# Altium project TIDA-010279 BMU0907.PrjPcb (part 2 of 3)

## Sheet TIDA-010279 BMU_stack0.SchDoc
size 558 x 431 mm; Date: Not shown in title block; ApprovedBy: Not shown in title block; CheckedBy: Not shown in title block; Author: Not shown in title block; CompanyName: Not shown in title block; Engineer: Not shown in title block; Organization: Not shown in title block; Address1: Not shown in title block; Address2: Not shown in title block; Address3: Not shown in title block; Address4: Not shown in title block; DocumentNumber: 2; Revision: Use project parameter SCH_Rev; SheetNumber: 2; SheetTotal: 4; PageSetup: Record=PageOptions¦CenterHorizontal=True¦CenterVertical=True¦PrintScale=1.00¦XCorrection=1.00¦YCorrection=1.00¦PrintKind=0¦BorderSize=5000000¦LeftOffset=0¦BottomOffset=0¦Orientation=2¦PaperLength=1000¦PaperWidth=1000¦Scale=100¦PaperSource=15¦PrintQuality=600¦MediaType=1¦DitherType=10¦PaperKind=Letter¦PrintScaleMode=1
Used 4 times, as channels A1, A2, A3, A4. Parts and nets are listed once, with the designators drawn on the sheet.
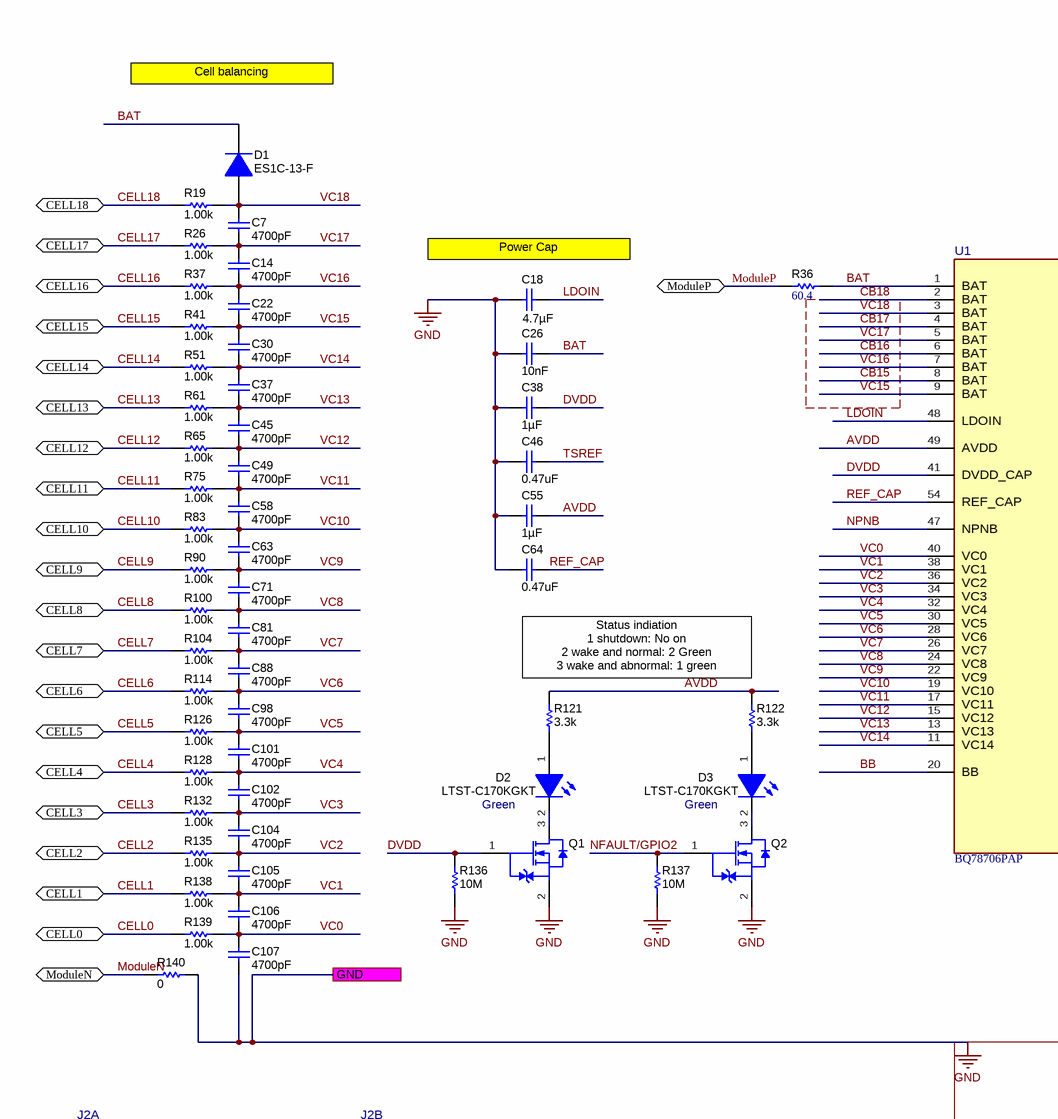
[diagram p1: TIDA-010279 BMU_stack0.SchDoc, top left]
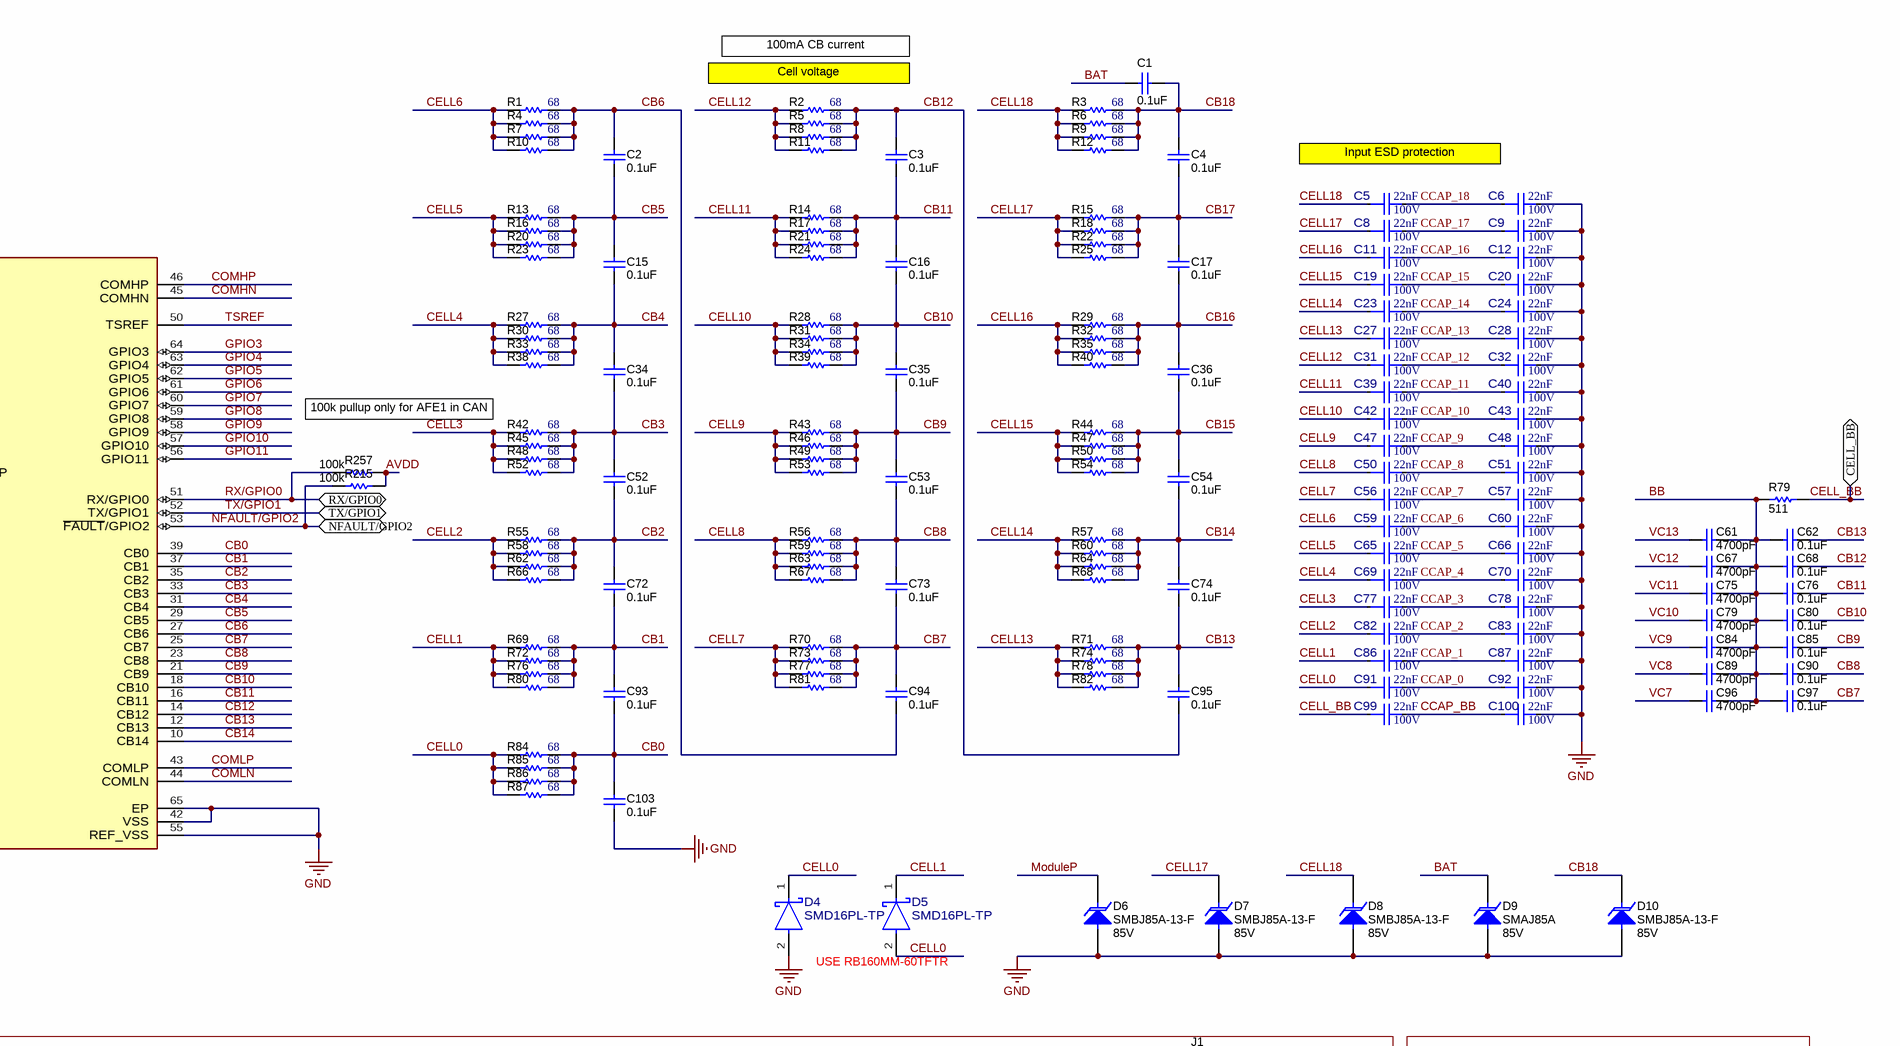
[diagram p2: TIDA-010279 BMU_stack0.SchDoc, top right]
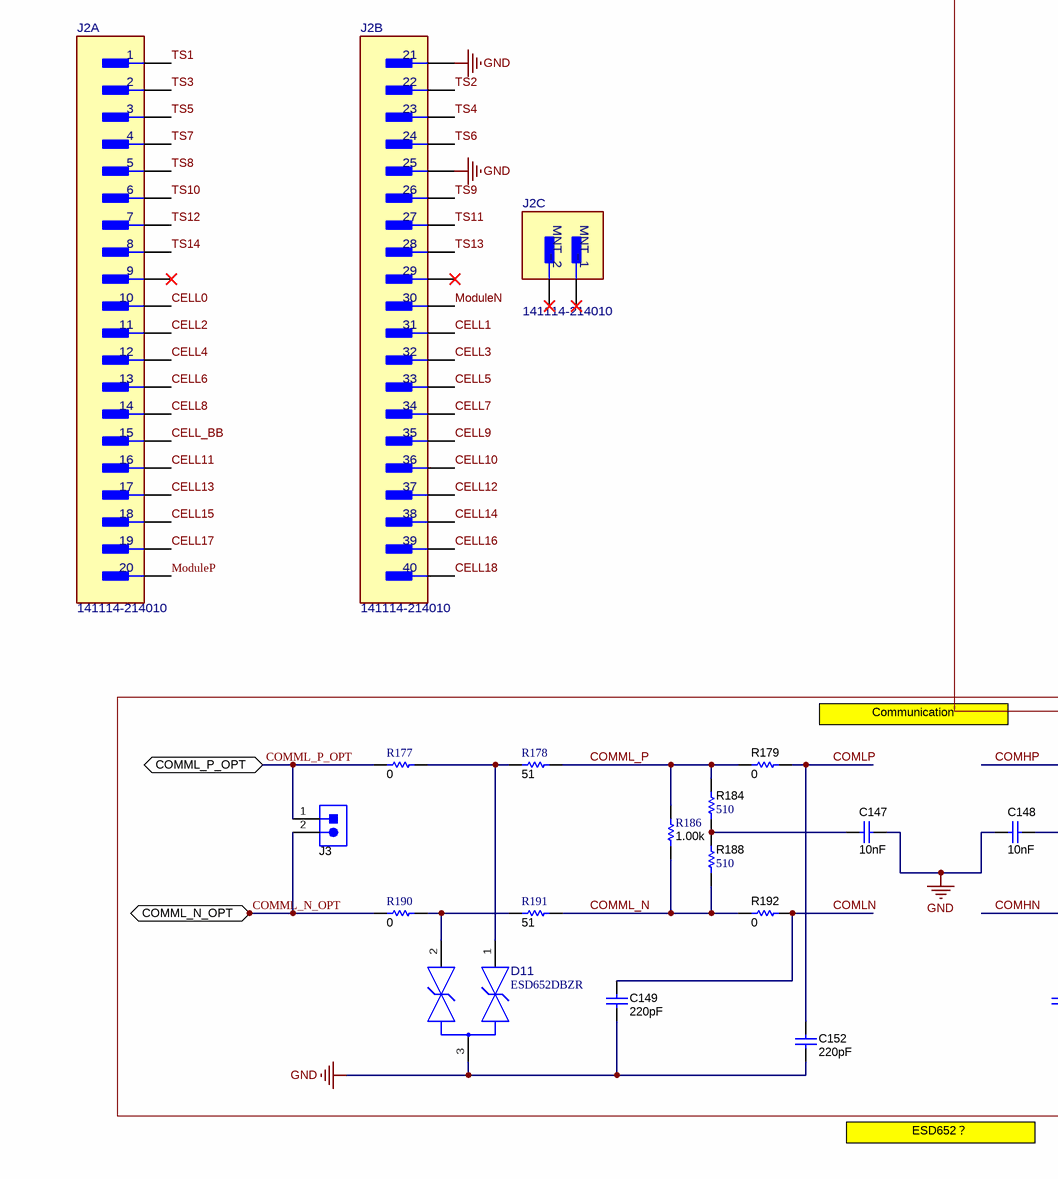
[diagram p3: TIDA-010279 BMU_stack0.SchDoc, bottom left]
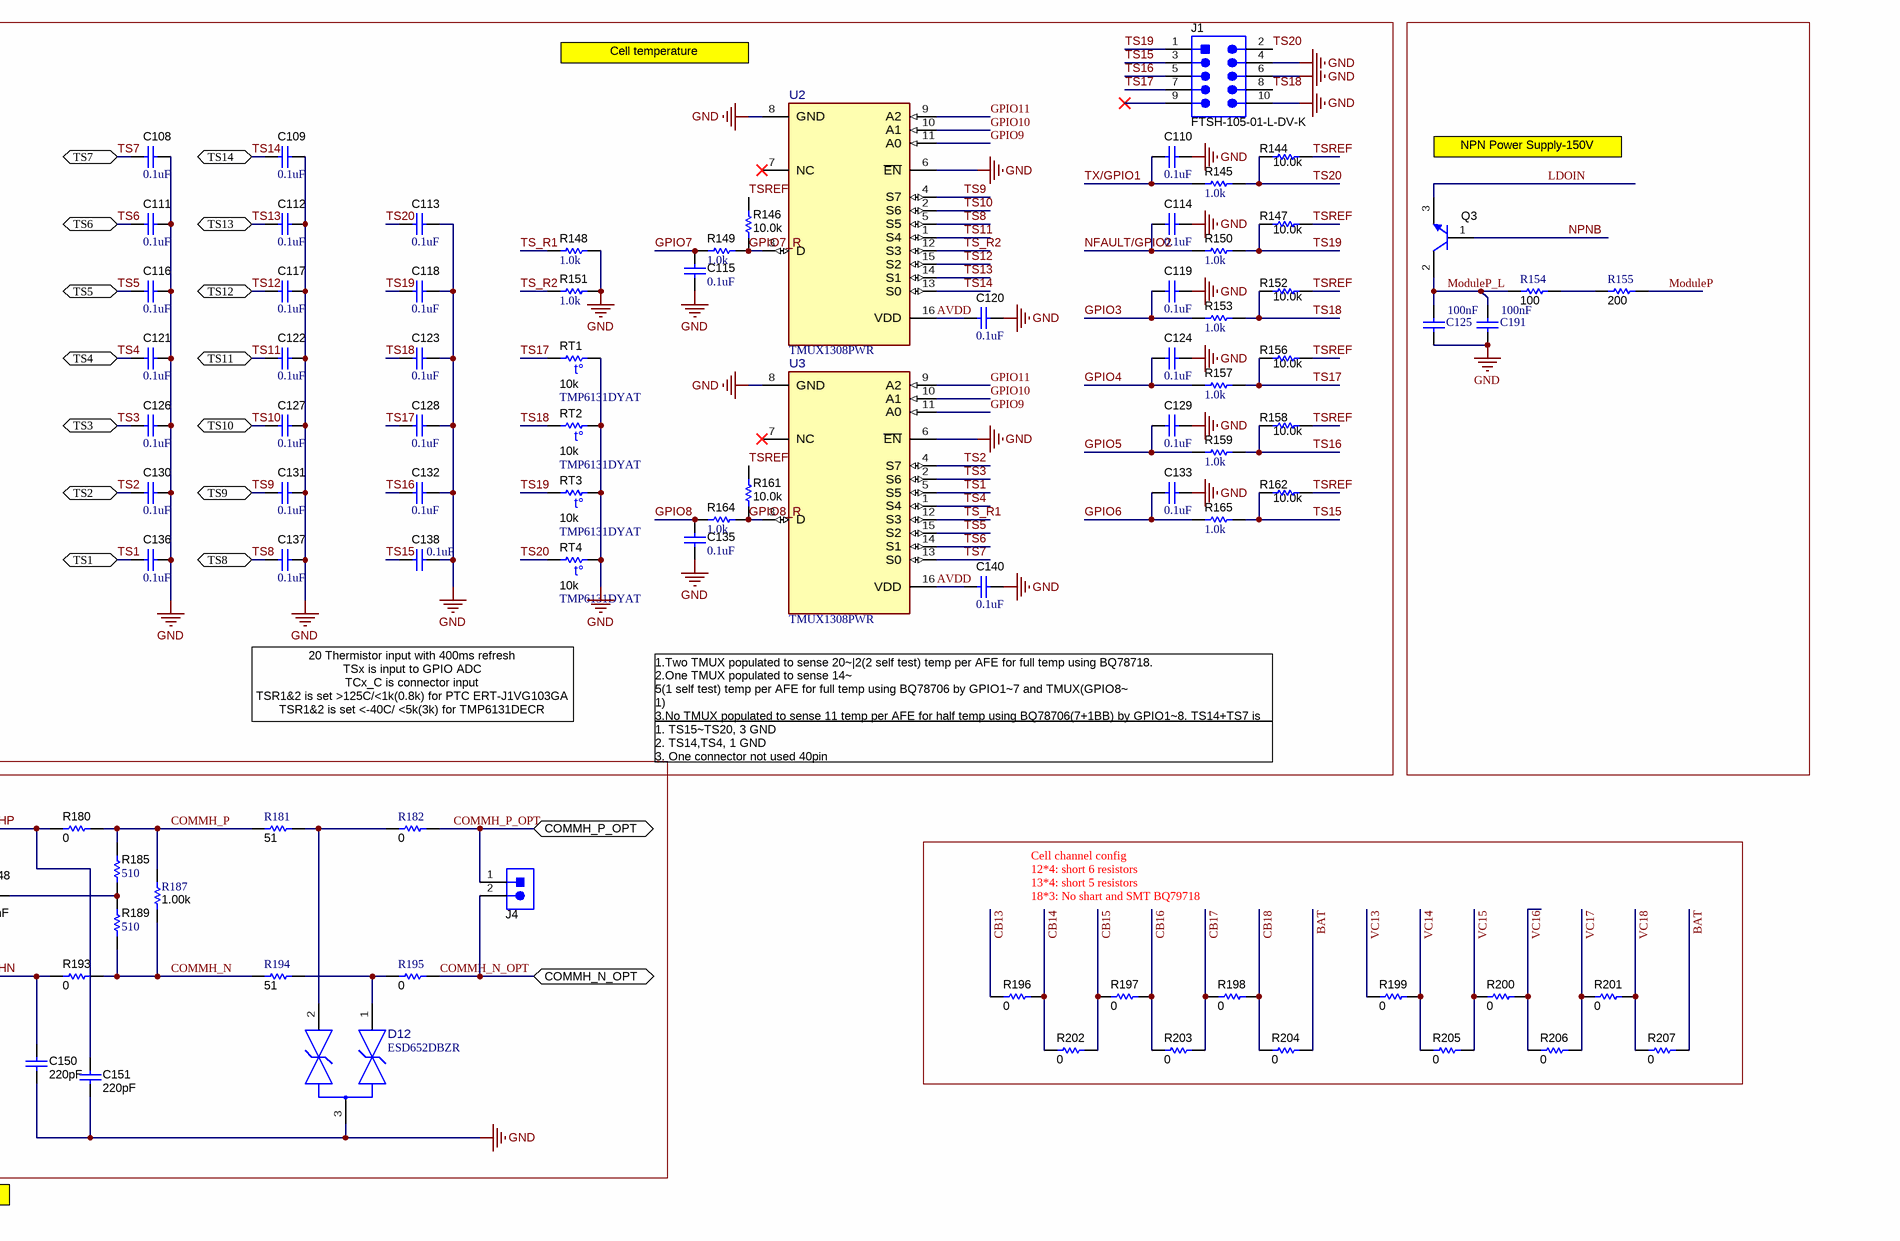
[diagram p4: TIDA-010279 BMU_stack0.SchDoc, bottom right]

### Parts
C1  ValueDisplayed: 0.1uF  [0402]  (hidden comment: GCM155R71H104KE02D)
C2  ValueDisplayed: 0.1uF  [0402]  (hidden comment: GCM155R71H104KE02D)
C3  ValueDisplayed: 0.1uF  [0402]  (hidden comment: GCM155R71H104KE02D)
C4  ValueDisplayed: 0.1uF  [0402]  (hidden comment: GCM155R71H104KE02D)
C5  VDC_V: 100V  Cap_F: 22nF  [FP-CGA3E2X7R2A223K080AA_0603-MFG]  (hidden comment: CGA3E2X7R2A223K080AA)
C6  VDC_V: 100V  Cap_F: 22nF  [FP-CGA3E2X7R2A223K080AA_0603-MFG]  (hidden comment: CGA3E2X7R2A223K080AA)
C7  ValueDisplayed: 4700pF  [0402]  (hidden comment: GCM155R71H472KA37D)
C8  VDC_V: 100V  Cap_F: 22nF  [FP-CGA3E2X7R2A223K080AA_0603-MFG]  (hidden comment: CGA3E2X7R2A223K080AA)
C9  VDC_V: 100V  Cap_F: 22nF  [FP-CGA3E2X7R2A223K080AA_0603-MFG]  (hidden comment: CGA3E2X7R2A223K080AA)
C11  VDC_V: 100V  Cap_F: 22nF  [FP-CGA3E2X7R2A223K080AA_0603-MFG]  (hidden comment: CGA3E2X7R2A223K080AA)
C12  VDC_V: 100V  Cap_F: 22nF  [FP-CGA3E2X7R2A223K080AA_0603-MFG]  (hidden comment: CGA3E2X7R2A223K080AA)
C14  ValueDisplayed: 4700pF  [0402]  (hidden comment: GCM155R71H472KA37D)
C15  ValueDisplayed: 0.1uF  [0402]  (hidden comment: GCM155R71H104KE02D)
C16  ValueDisplayed: 0.1uF  [0402]  (hidden comment: GCM155R71H104KE02D)
C17  ValueDisplayed: 0.1uF  [0402]  (hidden comment: GCM155R71H104KE02D)
C18  Cap_F: 4.7µF  [0805_HV]  (hidden comment: C0805C475J8RACAUTO)
C19  VDC_V: 100V  Cap_F: 22nF  [FP-CGA3E2X7R2A223K080AA_0603-MFG]  (hidden comment: CGA3E2X7R2A223K080AA)
C20  VDC_V: 100V  Cap_F: 22nF  [FP-CGA3E2X7R2A223K080AA_0603-MFG]  (hidden comment: CGA3E2X7R2A223K080AA)
C22  ValueDisplayed: 4700pF  [0402]  (hidden comment: GCM155R71H472KA37D)
C23  VDC_V: 100V  Cap_F: 22nF  [FP-CGA3E2X7R2A223K080AA_0603-MFG]  (hidden comment: CGA3E2X7R2A223K080AA)
C24  VDC_V: 100V  Cap_F: 22nF  [FP-CGA3E2X7R2A223K080AA_0603-MFG]  (hidden comment: CGA3E2X7R2A223K080AA)
C26  Cap_F: 10nF  [0603_HV]  (hidden comment: GCM188R72A103KA37J)
C27  VDC_V: 100V  Cap_F: 22nF  [FP-CGA3E2X7R2A223K080AA_0603-MFG]  (hidden comment: CGA3E2X7R2A223K080AA)
C28  VDC_V: 100V  Cap_F: 22nF  [FP-CGA3E2X7R2A223K080AA_0603-MFG]  (hidden comment: CGA3E2X7R2A223K080AA)
C30  ValueDisplayed: 4700pF  [0402]  (hidden comment: GCM155R71H472KA37D)
C31  VDC_V: 100V  Cap_F: 22nF  [FP-CGA3E2X7R2A223K080AA_0603-MFG]  (hidden comment: CGA3E2X7R2A223K080AA)
C32  VDC_V: 100V  Cap_F: 22nF  [FP-CGA3E2X7R2A223K080AA_0603-MFG]  (hidden comment: CGA3E2X7R2A223K080AA)
C34  ValueDisplayed: 0.1uF  [0402]  (hidden comment: GCM155R71H104KE02D)
C35  ValueDisplayed: 0.1uF  [0402]  (hidden comment: GCM155R71H104KE02D)
C36  ValueDisplayed: 0.1uF  [0402]  (hidden comment: GCM155R71H104KE02D)
C37  ValueDisplayed: 4700pF  [0402]  (hidden comment: GCM155R71H472KA37D)
C38  Cap_F: 1µF  [0603]  (hidden comment: GCM188R71C105KA64D)
C39  VDC_V: 100V  Cap_F: 22nF  [FP-CGA3E2X7R2A223K080AA_0603-MFG]  (hidden comment: CGA3E2X7R2A223K080AA)
C40  VDC_V: 100V  Cap_F: 22nF  [FP-CGA3E2X7R2A223K080AA_0603-MFG]  (hidden comment: CGA3E2X7R2A223K080AA)
C42  VDC_V: 100V  Cap_F: 22nF  [FP-CGA3E2X7R2A223K080AA_0603-MFG]  (hidden comment: CGA3E2X7R2A223K080AA)
C43  VDC_V: 100V  Cap_F: 22nF  [FP-CGA3E2X7R2A223K080AA_0603-MFG]  (hidden comment: CGA3E2X7R2A223K080AA)
C45  ValueDisplayed: 4700pF  [0402]  (hidden comment: GCM155R71H472KA37D)
C46  ValueDisplayed: 0.47uF  [0603]  (hidden comment: GCM188R71C474KA55D)
C47  VDC_V: 100V  Cap_F: 22nF  [FP-CGA3E2X7R2A223K080AA_0603-MFG]  (hidden comment: CGA3E2X7R2A223K080AA)
C48  VDC_V: 100V  Cap_F: 22nF  [FP-CGA3E2X7R2A223K080AA_0603-MFG]  (hidden comment: CGA3E2X7R2A223K080AA)
C49  ValueDisplayed: 4700pF  [0402]  (hidden comment: GCM155R71H472KA37D)
C50  VDC_V: 100V  Cap_F: 22nF  [FP-CGA3E2X7R2A223K080AA_0603-MFG]  (hidden comment: CGA3E2X7R2A223K080AA)
C51  VDC_V: 100V  Cap_F: 22nF  [FP-CGA3E2X7R2A223K080AA_0603-MFG]  (hidden comment: CGA3E2X7R2A223K080AA)
C52  ValueDisplayed: 0.1uF  [0402]  (hidden comment: GCM155R71H104KE02D)
C53  ValueDisplayed: 0.1uF  [0402]  (hidden comment: GCM155R71H104KE02D)
C54  ValueDisplayed: 0.1uF  [0402]  (hidden comment: GCM155R71H104KE02D)
C55  Cap_F: 1µF  [0603]  (hidden comment: GCM188R71C105KA64D)
C56  VDC_V: 100V  Cap_F: 22nF  [FP-CGA3E2X7R2A223K080AA_0603-MFG]  (hidden comment: CGA3E2X7R2A223K080AA)
C57  VDC_V: 100V  Cap_F: 22nF  [FP-CGA3E2X7R2A223K080AA_0603-MFG]  (hidden comment: CGA3E2X7R2A223K080AA)
C58  ValueDisplayed: 4700pF  [0402]  (hidden comment: GCM155R71H472KA37D)
C59  VDC_V: 100V  Cap_F: 22nF  [FP-CGA3E2X7R2A223K080AA_0603-MFG]  (hidden comment: CGA3E2X7R2A223K080AA)
C60  VDC_V: 100V  Cap_F: 22nF  [FP-CGA3E2X7R2A223K080AA_0603-MFG]  (hidden comment: CGA3E2X7R2A223K080AA)
C61  ValueDisplayed: 4700pF  [0402]  (hidden comment: GCM155R71H472KA37D)
C62  ValueDisplayed: 0.1uF  [0402]  (hidden comment: GCM155R71H104KE02D)
C63  ValueDisplayed: 4700pF  [0402]  (hidden comment: GCM155R71H472KA37D)
C64  ValueDisplayed: 0.47uF  [0603]  (hidden comment: GCM188R71C474KA55D)
C65  VDC_V: 100V  Cap_F: 22nF  [FP-CGA3E2X7R2A223K080AA_0603-MFG]  (hidden comment: CGA3E2X7R2A223K080AA)
C66  VDC_V: 100V  Cap_F: 22nF  [FP-CGA3E2X7R2A223K080AA_0603-MFG]  (hidden comment: CGA3E2X7R2A223K080AA)
C67  ValueDisplayed: 4700pF  [0402]  (hidden comment: GCM155R71H472KA37D)
C68  ValueDisplayed: 0.1uF  [0402]  (hidden comment: GCM155R71H104KE02D)
C69  VDC_V: 100V  Cap_F: 22nF  [FP-CGA3E2X7R2A223K080AA_0603-MFG]  (hidden comment: CGA3E2X7R2A223K080AA)
C70  VDC_V: 100V  Cap_F: 22nF  [FP-CGA3E2X7R2A223K080AA_0603-MFG]  (hidden comment: CGA3E2X7R2A223K080AA)
C71  ValueDisplayed: 4700pF  [0402]  (hidden comment: GCM155R71H472KA37D)
C72  ValueDisplayed: 0.1uF  [0402]  (hidden comment: GCM155R71H104KE02D)
C73  ValueDisplayed: 0.1uF  [0402]  (hidden comment: GCM155R71H104KE02D)
C74  ValueDisplayed: 0.1uF  [0402]  (hidden comment: GCM155R71H104KE02D)
C75  ValueDisplayed: 4700pF  [0402]  (hidden comment: GCM155R71H472KA37D)
C76  ValueDisplayed: 0.1uF  [0402]  (hidden comment: GCM155R71H104KE02D)
C77  VDC_V: 100V  Cap_F: 22nF  [FP-CGA3E2X7R2A223K080AA_0603-MFG]  (hidden comment: CGA3E2X7R2A223K080AA)
C78  VDC_V: 100V  Cap_F: 22nF  [FP-CGA3E2X7R2A223K080AA_0603-MFG]  (hidden comment: CGA3E2X7R2A223K080AA)
C79  ValueDisplayed: 4700pF  [0402]  (hidden comment: GCM155R71H472KA37D)
C80  ValueDisplayed: 0.1uF  [0402]  (hidden comment: GCM155R71H104KE02D)
C81  ValueDisplayed: 4700pF  [0402]  (hidden comment: GCM155R71H472KA37D)
C82  VDC_V: 100V  Cap_F: 22nF  [FP-CGA3E2X7R2A223K080AA_0603-MFG]  (hidden comment: CGA3E2X7R2A223K080AA)
C83  VDC_V: 100V  Cap_F: 22nF  [FP-CGA3E2X7R2A223K080AA_0603-MFG]  (hidden comment: CGA3E2X7R2A223K080AA)
C84  ValueDisplayed: 4700pF  [0402]  (hidden comment: GCM155R71H472KA37D)
C85  ValueDisplayed: 0.1uF  [0402]  (hidden comment: GCM155R71H104KE02D)
C86  VDC_V: 100V  Cap_F: 22nF  [FP-CGA3E2X7R2A223K080AA_0603-MFG]  (hidden comment: CGA3E2X7R2A223K080AA)
C87  VDC_V: 100V  Cap_F: 22nF  [FP-CGA3E2X7R2A223K080AA_0603-MFG]  (hidden comment: CGA3E2X7R2A223K080AA)
C88  ValueDisplayed: 4700pF  [0402]  (hidden comment: GCM155R71H472KA37D)
C89  ValueDisplayed: 4700pF  [0402]  (hidden comment: GCM155R71H472KA37D)
C90  ValueDisplayed: 0.1uF  [0402]  (hidden comment: GCM155R71H104KE02D)
C91  VDC_V: 100V  Cap_F: 22nF  [FP-CGA3E2X7R2A223K080AA_0603-MFG]  (hidden comment: CGA3E2X7R2A223K080AA)
C92  VDC_V: 100V  Cap_F: 22nF  [FP-CGA3E2X7R2A223K080AA_0603-MFG]  (hidden comment: CGA3E2X7R2A223K080AA)
C93  ValueDisplayed: 0.1uF  [0402]  (hidden comment: GCM155R71H104KE02D)
C94  ValueDisplayed: 0.1uF  [0402]  (hidden comment: GCM155R71H104KE02D)
C95  ValueDisplayed: 0.1uF  [0402]  (hidden comment: GCM155R71H104KE02D)
C96  ValueDisplayed: 4700pF  [0402]  (hidden comment: GCM155R71H472KA37D)
C97  ValueDisplayed: 0.1uF  [0402]  (hidden comment: GCM155R71H104KE02D)
C98  ValueDisplayed: 4700pF  [0402]  (hidden comment: GCM155R71H472KA37D)
C99  VDC_V: 100V  Cap_F: 22nF  [FP-CGA3E2X7R2A223K080AA_0603-MFG]  (hidden comment: CGA3E2X7R2A223K080AA)
C100  VDC_V: 100V  Cap_F: 22nF  [FP-CGA3E2X7R2A223K080AA_0603-MFG]  (hidden comment: CGA3E2X7R2A223K080AA)
C101  ValueDisplayed: 4700pF  [0402]  (hidden comment: GCM155R71H472KA37D)
C102  ValueDisplayed: 4700pF  [0402]  (hidden comment: GCM155R71H472KA37D)
C103  ValueDisplayed: 0.1uF  [0402]  (hidden comment: GCM155R71H104KE02D)
C104  ValueDisplayed: 4700pF  [0402]  (hidden comment: GCM155R71H472KA37D)
C105  ValueDisplayed: 4700pF  [0402]  (hidden comment: GCM155R71H472KA37D)
C106  ValueDisplayed: 4700pF  [0402]  (hidden comment: GCM155R71H472KA37D)
C107  ValueDisplayed: 4700pF  [0402]  (hidden comment: GCM155R71H472KA37D)
C108  ValueDisplayed: 0.1uF  [0402]  (hidden comment: GCM155R71H104KE02D)
C109  ValueDisplayed: 0.1uF  [0402]  (hidden comment: GCM155R71H104KE02D)
C110  ValueDisplayed: 0.1uF  [0402]  (hidden comment: GCM155R71H104KE02D)
C111  ValueDisplayed: 0.1uF  [0402]  (hidden comment: GCM155R71H104KE02D)
C112  ValueDisplayed: 0.1uF  [0402]  (hidden comment: GCM155R71H104KE02D)
C113  ValueDisplayed: 0.1uF  [0402]  (hidden comment: GCM155R71H104KE02D)
C114  ValueDisplayed: 0.1uF  [0402]  (hidden comment: GCM155R71H104KE02D)
C115  ValueDisplayed: 0.1uF  [0402]  (hidden comment: GCM155R71H104KE02D)
C116  ValueDisplayed: 0.1uF  [0402]  (hidden comment: GCM155R71H104KE02D)
C117  ValueDisplayed: 0.1uF  [0402]  (hidden comment: GCM155R71H104KE02D)
C118  ValueDisplayed: 0.1uF  [0402]  (hidden comment: GCM155R71H104KE02D)
C119  ValueDisplayed: 0.1uF  [0402]  (hidden comment: GCM155R71H104KE02D)
C120  ValueDisplayed: 0.1uF  [0402]  (hidden comment: GCM155R71H104KE02D)
C121  ValueDisplayed: 0.1uF  [0402]  (hidden comment: GCM155R71H104KE02D)
C122  ValueDisplayed: 0.1uF  [0402]  (hidden comment: GCM155R71H104KE02D)
C123  ValueDisplayed: 0.1uF  [0402]  (hidden comment: GCM155R71H104KE02D)
C124  ValueDisplayed: 0.1uF  [0402]  (hidden comment: GCM155R71H104KE02D)
C125  Cap_F: 100nF  [WCAP-CSGP_1206_L3.2W1.6H1.25]  (hidden comment: 885012208118)
C126  ValueDisplayed: 0.1uF  [0402]  (hidden comment: GCM155R71H104KE02D)
C127  ValueDisplayed: 0.1uF  [0402]  (hidden comment: GCM155R71H104KE02D)
C128  ValueDisplayed: 0.1uF  [0402]  (hidden comment: GCM155R71H104KE02D)
C129  ValueDisplayed: 0.1uF  [0402]  (hidden comment: GCM155R71H104KE02D)
C130  ValueDisplayed: 0.1uF  [0402]  (hidden comment: GCM155R71H104KE02D)
C131  ValueDisplayed: 0.1uF  [0402]  (hidden comment: GCM155R71H104KE02D)
C132  ValueDisplayed: 0.1uF  [0402]  (hidden comment: GCM155R71H104KE02D)
C133  ValueDisplayed: 0.1uF  [0402]  (hidden comment: GCM155R71H104KE02D)
C135  ValueDisplayed: 0.1uF  [0402]  (hidden comment: GCM155R71H104KE02D)
C136  ValueDisplayed: 0.1uF  [0402]  (hidden comment: GCM155R71H104KE02D)
C137  ValueDisplayed: 0.1uF  [0402]  (hidden comment: GCM155R71H104KE02D)
C138  ValueDisplayed: 0.1uF  [0402]  (hidden comment: GCM155R71H104KE02D)
C140  ValueDisplayed: 0.1uF  [0402]  (hidden comment: GCM155R71H104KE02D)
C147  Cap_F: 10nF  [0603]  (hidden comment: GCM188R71H103KA37D)
C148  Cap_F: 10nF  [0603]  (hidden comment: GCM188R71H103KA37D)
C149  Cap_F: 220pF  [0603]  (hidden comment: CL10B221JB8NNNC)
C150  Cap_F: 220pF  [0603]  (hidden comment: CL10B221JB8NNNC)
C151  Cap_F: 220pF  [0603]  (hidden comment: CL10B221JB8NNNC)
C152  Cap_F: 220pF  [0603]  (hidden comment: CL10B221JB8NNNC)
C191  Cap_F: 100nF  [WCAP-CSGP_1206_L3.2W1.6H1.25]  (hidden comment: 885012208118)
D1  ES1C-13-F  [SMA]
D2  LTST-C170KGKT  value Green  [LTST-C170KGKT_Green]
D3  LTST-C170KGKT  value Green  [LTST-C170KGKT_Green]
D4  SMD16PL-TP  [FP-SMD16PL-TP_SOD123FL-MFG]
D5  SMD16PL-TP  [FP-SMD16PL-TP_SOD123FL-MFG]
D6  SMBJ85A-13-F  value 85V  [SMB]
D7  SMBJ85A-13-F  value 85V  [SMB]
D8  SMBJ85A-13-F  value 85V  [SMB]
D9  SMAJ85A  value 85V  [SMA]
D10  SMBJ85A-13-F  value 85V  [SMB]
D11  ESD652DBZR  [DBZ0003A-MFG]
D12  ESD652DBZR  [DBZ0003A-MFG]
J1  FTSH-105-01-L-DV-K  [Samtec_FTSH-105-01-x-DV-K]
J2  141114-214010  [FP-141114-214010_HDR40-MFG]  (parts A,B,C of 3)
J3  PEC02SAAN  [CONN_PEC02SAAN]  (value not drawn)
J4  PEC02SAAN  [CONN_PEC02SAAN]  (value not drawn)
Q1  RE1C002UNTCL  [SC-89]  (value not drawn)
Q2  RE1C002UNTCL  [SC-89]  (value not drawn)
Q3  CMP-0000504-4  [DPAK]  (value not drawn)
R1  ValueDisplayed: 68  [0805_HV]  (hidden comment: HPCR0805J68R0KT)
R2  ValueDisplayed: 68  [0805_HV]  (hidden comment: HPCR0805J68R0KT)
R3  ValueDisplayed: 68  [0805_HV]  (hidden comment: HPCR0805J68R0KT)
R4  ValueDisplayed: 68  [0805_HV]  (hidden comment: HPCR0805J68R0KT)
R5  ValueDisplayed: 68  [0805_HV]  (hidden comment: HPCR0805J68R0KT)
R6  ValueDisplayed: 68  [0805_HV]  (hidden comment: HPCR0805J68R0KT)
R7  ValueDisplayed: 68  [0805_HV]  (hidden comment: HPCR0805J68R0KT)
R8  ValueDisplayed: 68  [0805_HV]  (hidden comment: HPCR0805J68R0KT)
R9  ValueDisplayed: 68  [0805_HV]  (hidden comment: HPCR0805J68R0KT)
R10  ValueDisplayed: 68  [0805_HV]  (hidden comment: HPCR0805J68R0KT)
R11  ValueDisplayed: 68  [0805_HV]  (hidden comment: HPCR0805J68R0KT)
R12  ValueDisplayed: 68  [0805_HV]  (hidden comment: HPCR0805J68R0KT)
R13  ValueDisplayed: 68  [0805_HV]  (hidden comment: HPCR0805J68R0KT)
R14  ValueDisplayed: 68  [0805_HV]  (hidden comment: HPCR0805J68R0KT)
R15  ValueDisplayed: 68  [0805_HV]  (hidden comment: HPCR0805J68R0KT)
R16  ValueDisplayed: 68  [0805_HV]  (hidden comment: HPCR0805J68R0KT)
R17  ValueDisplayed: 68  [0805_HV]  (hidden comment: HPCR0805J68R0KT)
R18  ValueDisplayed: 68  [0805_HV]  (hidden comment: HPCR0805J68R0KT)
R19  ValueDisplayed: 1.00k  [0402]  (hidden comment: CRCW04021K00FKED)
R20  ValueDisplayed: 68  [0805_HV]  (hidden comment: HPCR0805J68R0KT)
R21  ValueDisplayed: 68  [0805_HV]  (hidden comment: HPCR0805J68R0KT)
R22  ValueDisplayed: 68  [0805_HV]  (hidden comment: HPCR0805J68R0KT)
R23  ValueDisplayed: 68  [0805_HV]  (hidden comment: HPCR0805J68R0KT)
R24  ValueDisplayed: 68  [0805_HV]  (hidden comment: HPCR0805J68R0KT)
R25  ValueDisplayed: 68  [0805_HV]  (hidden comment: HPCR0805J68R0KT)
R26  ValueDisplayed: 1.00k  [0402]  (hidden comment: CRCW04021K00FKED)
R27  ValueDisplayed: 68  [0805_HV]  (hidden comment: HPCR0805J68R0KT)
R28  ValueDisplayed: 68  [0805_HV]  (hidden comment: HPCR0805J68R0KT)
R29  ValueDisplayed: 68  [0805_HV]  (hidden comment: HPCR0805J68R0KT)
R30  ValueDisplayed: 68  [0805_HV]  (hidden comment: HPCR0805J68R0KT)
R31  ValueDisplayed: 68  [0805_HV]  (hidden comment: HPCR0805J68R0KT)
R32  ValueDisplayed: 68  [0805_HV]  (hidden comment: HPCR0805J68R0KT)
R33  ValueDisplayed: 68  [0805_HV]  (hidden comment: HPCR0805J68R0KT)
R34  ValueDisplayed: 68  [0805_HV]  (hidden comment: HPCR0805J68R0KT)
R35  ValueDisplayed: 68  [0805_HV]  (hidden comment: HPCR0805J68R0KT)
R36  ValueDisplayed: 60.4  [0805_HV]  (hidden comment: CRCW080560R4FKEA)
R37  ValueDisplayed: 1.00k  [0402]  (hidden comment: CRCW04021K00FKED)
R38  ValueDisplayed: 68  [0805_HV]  (hidden comment: HPCR0805J68R0KT)
R39  ValueDisplayed: 68  [0805_HV]  (hidden comment: HPCR0805J68R0KT)
R40  ValueDisplayed: 68  [0805_HV]  (hidden comment: HPCR0805J68R0KT)
R41  ValueDisplayed: 1.00k  [0402]  (hidden comment: CRCW04021K00FKED)
R42  ValueDisplayed: 68  [0805_HV]  (hidden comment: HPCR0805J68R0KT)
R43  ValueDisplayed: 68  [0805_HV]  (hidden comment: HPCR0805J68R0KT)
R44  ValueDisplayed: 68  [0805_HV]  (hidden comment: HPCR0805J68R0KT)
R45  ValueDisplayed: 68  [0805_HV]  (hidden comment: HPCR0805J68R0KT)
R46  ValueDisplayed: 68  [0805_HV]  (hidden comment: HPCR0805J68R0KT)
R47  ValueDisplayed: 68  [0805_HV]  (hidden comment: HPCR0805J68R0KT)
R48  ValueDisplayed: 68  [0805_HV]  (hidden comment: HPCR0805J68R0KT)
R49  ValueDisplayed: 68  [0805_HV]  (hidden comment: HPCR0805J68R0KT)
R50  ValueDisplayed: 68  [0805_HV]  (hidden comment: HPCR0805J68R0KT)
R51  ValueDisplayed: 1.00k  [0402]  (hidden comment: CRCW04021K00FKED)
R52  ValueDisplayed: 68  [0805_HV]  (hidden comment: HPCR0805J68R0KT)
R53  ValueDisplayed: 68  [0805_HV]  (hidden comment: HPCR0805J68R0KT)
R54  ValueDisplayed: 68  [0805_HV]  (hidden comment: HPCR0805J68R0KT)
R55  ValueDisplayed: 68  [0805_HV]  (hidden comment: HPCR0805J68R0KT)
R56  ValueDisplayed: 68  [0805_HV]  (hidden comment: HPCR0805J68R0KT)
R57  ValueDisplayed: 68  [0805_HV]  (hidden comment: HPCR0805J68R0KT)
R58  ValueDisplayed: 68  [0805_HV]  (hidden comment: HPCR0805J68R0KT)
R59  ValueDisplayed: 68  [0805_HV]  (hidden comment: HPCR0805J68R0KT)
R60  ValueDisplayed: 68  [0805_HV]  (hidden comment: HPCR0805J68R0KT)
R61  ValueDisplayed: 1.00k  [0402]  (hidden comment: CRCW04021K00FKED)
R62  ValueDisplayed: 68  [0805_HV]  (hidden comment: HPCR0805J68R0KT)
R63  ValueDisplayed: 68  [0805_HV]  (hidden comment: HPCR0805J68R0KT)
R64  ValueDisplayed: 68  [0805_HV]  (hidden comment: HPCR0805J68R0KT)
R65  ValueDisplayed: 1.00k  [0402]  (hidden comment: CRCW04021K00FKED)
R66  ValueDisplayed: 68  [0805_HV]  (hidden comment: HPCR0805J68R0KT)
R67  ValueDisplayed: 68  [0805_HV]  (hidden comment: HPCR0805J68R0KT)
R68  ValueDisplayed: 68  [0805_HV]  (hidden comment: HPCR0805J68R0KT)
R69  ValueDisplayed: 68  [0805_HV]  (hidden comment: HPCR0805J68R0KT)
R70  ValueDisplayed: 68  [0805_HV]  (hidden comment: HPCR0805J68R0KT)
R71  ValueDisplayed: 68  [0805_HV]  (hidden comment: HPCR0805J68R0KT)
R72  ValueDisplayed: 68  [0805_HV]  (hidden comment: HPCR0805J68R0KT)
R73  ValueDisplayed: 68  [0805_HV]  (hidden comment: HPCR0805J68R0KT)
R74  ValueDisplayed: 68  [0805_HV]  (hidden comment: HPCR0805J68R0KT)
R75  ValueDisplayed: 1.00k  [0402]  (hidden comment: CRCW04021K00FKED)
R76  ValueDisplayed: 68  [0805_HV]  (hidden comment: HPCR0805J68R0KT)
R77  ValueDisplayed: 68  [0805_HV]  (hidden comment: HPCR0805J68R0KT)
R78  ValueDisplayed: 68  [0805_HV]  (hidden comment: HPCR0805J68R0KT)
R79  ValueDisplayed: 511  [0402]  (hidden comment: CRCW0402511RFKED)
R80  ValueDisplayed: 68  [0805_HV]  (hidden comment: HPCR0805J68R0KT)
R81  ValueDisplayed: 68  [0805_HV]  (hidden comment: HPCR0805J68R0KT)
R82  ValueDisplayed: 68  [0805_HV]  (hidden comment: HPCR0805J68R0KT)
R83  ValueDisplayed: 1.00k  [0402]  (hidden comment: CRCW04021K00FKED)
R84  ValueDisplayed: 68  [0805_HV]  (hidden comment: HPCR0805J68R0KT)
R85  ValueDisplayed: 68  [0805_HV]  (hidden comment: HPCR0805J68R0KT)
R86  ValueDisplayed: 68  [0805_HV]  (hidden comment: HPCR0805J68R0KT)
R87  ValueDisplayed: 68  [0805_HV]  (hidden comment: HPCR0805J68R0KT)
R90  ValueDisplayed: 1.00k  [0402]  (hidden comment: CRCW04021K00FKED)
R100  ValueDisplayed: 1.00k  [0402]  (hidden comment: CRCW04021K00FKED)
R104  ValueDisplayed: 1.00k  [0402]  (hidden comment: CRCW04021K00FKED)
R114  ValueDisplayed: 1.00k  [0402]  (hidden comment: CRCW04021K00FKED)
R121  ValueDisplayed: 3.3k  [0402]  (hidden comment: CRCW04023K30JNED)
R122  ValueDisplayed: 3.3k  [0402]  (hidden comment: CRCW04023K30JNED)
R126  ValueDisplayed: 1.00k  [0402]  (hidden comment: CRCW04021K00FKED)
R128  ValueDisplayed: 1.00k  [0402]  (hidden comment: CRCW04021K00FKED)
R132  ValueDisplayed: 1.00k  [0402]  (hidden comment: CRCW04021K00FKED)
R135  ValueDisplayed: 1.00k  [0402]  (hidden comment: CRCW04021K00FKED)
R136  ValueDisplayed: 10M  [0603]  (hidden comment: CRCW060310M0JNEA)
R137  ValueDisplayed: 10M  [0603]  (hidden comment: CRCW060310M0JNEA)
R138  ValueDisplayed: 1.00k  [0402]  (hidden comment: CRCW04021K00FKED)
R139  ValueDisplayed: 1.00k  [0402]  (hidden comment: CRCW04021K00FKED)
R140  ValueDisplayed: 0  [0402]  (hidden comment: CRCW04020000Z0ED)
R144  ValueDisplayed: 10.0k  [0402]  (hidden comment: CRCW040210K0FKED)
R145  ValueDisplayed: 1.0k  [0402]  (hidden comment: CRCW04021K00JNED)
R146  ValueDisplayed: 10.0k  [0402]  (hidden comment: CRCW040210K0FKED)
R147  ValueDisplayed: 10.0k  [0402]  (hidden comment: CRCW040210K0FKED)
R148  ValueDisplayed: 1.0k  [0402]  (hidden comment: CRCW04021K00JNED)
R149  ValueDisplayed: 1.0k  [0402]  (hidden comment: CRCW04021K00JNED)
R150  ValueDisplayed: 1.0k  [0402]  (hidden comment: CRCW04021K00JNED)
R151  ValueDisplayed: 1.0k  [0402]  (hidden comment: CRCW04021K00JNED)
R152  ValueDisplayed: 10.0k  [0402]  (hidden comment: CRCW040210K0FKED)
R153  ValueDisplayed: 1.0k  [0402]  (hidden comment: CRCW04021K00JNED)
R154  ValueDisplayed: 100  [2010]  (hidden comment: CRCW2010100RFKEF)
R155  ValueDisplayed: 200  [2010]  (hidden comment: CRCW2010200RFKEF)
R156  ValueDisplayed: 10.0k  [0402]  (hidden comment: CRCW040210K0FKED)
R157  ValueDisplayed: 1.0k  [0402]  (hidden comment: CRCW04021K00JNED)
R158  ValueDisplayed: 10.0k  [0402]  (hidden comment: CRCW040210K0FKED)
R159  ValueDisplayed: 1.0k  [0402]  (hidden comment: CRCW04021K00JNED)
R161  ValueDisplayed: 10.0k  [0402]  (hidden comment: CRCW040210K0FKED)
R162  ValueDisplayed: 10.0k  [0402]  (hidden comment: CRCW040210K0FKED)
R164  ValueDisplayed: 1.0k  [0402]  (hidden comment: CRCW04021K00JNED)
R165  ValueDisplayed: 1.0k  [0402]  (hidden comment: CRCW04021K00JNED)
R177  ValueDisplayed: 0  [0603]  (hidden comment: RC0603JR-070RL)
R178  ValueDisplayed: 51  [0603]  (hidden comment: CRCW060351R0JNEA)
R179  ValueDisplayed: 0  [0603]  (hidden comment: ERJ-3GEY0R00V)
R180  ValueDisplayed: 0  [0603]  (hidden comment: ERJ-3GEY0R00V)
R181  ValueDisplayed: 51  [0603]  (hidden comment: CRCW060351R0JNEA)
R182  ValueDisplayed: 0  [0603]  (hidden comment: RC0603JR-070RL)
R184  ValueDisplayed: 510  [0603]  (hidden comment: CRCW0603510RJNEA)
R185  ValueDisplayed: 510  [0603]  (hidden comment: CRCW0603510RJNEA)
R186  ValueDisplayed: 1.00k  [0603]  (hidden comment: ERJ-3EKF1001V)
R187  ValueDisplayed: 1.00k  [0603]  (hidden comment: ERJ-3EKF1001V)
R188  ValueDisplayed: 510  [0603]  (hidden comment: CRCW0603510RJNEA)
R189  ValueDisplayed: 510  [0603]  (hidden comment: CRCW0603510RJNEA)
R190  ValueDisplayed: 0  [0603]  (hidden comment: RC0603JR-070RL)
R191  ValueDisplayed: 51  [0603]  (hidden comment: CRCW060351R0JNEA)
R192  ValueDisplayed: 0  [0603]  (hidden comment: ERJ-3GEY0R00V)
R193  ValueDisplayed: 0  [0603]  (hidden comment: ERJ-3GEY0R00V)
R194  ValueDisplayed: 51  [0603]  (hidden comment: CRCW060351R0JNEA)
R195  ValueDisplayed: 0  [0603]  (hidden comment: RC0603JR-070RL)
R196  ValueDisplayed: 0  [0402]  (hidden comment: CRCW04020000Z0ED)
R197  ValueDisplayed: 0  [0402]  (hidden comment: CRCW04020000Z0ED)
R198  ValueDisplayed: 0  [0402]  (hidden comment: CRCW04020000Z0ED)
R199  ValueDisplayed: 0  [0402]  (hidden comment: CRCW04020000Z0ED)
R200  ValueDisplayed: 0  [0402]  (hidden comment: CRCW04020000Z0ED)
R201  ValueDisplayed: 0  [0402]  (hidden comment: CRCW04020000Z0ED)
R202  ValueDisplayed: 0  [0402]  (hidden comment: CRCW04020000Z0ED)
R203  ValueDisplayed: 0  [0402]  (hidden comment: CRCW04020000Z0ED)
R204  ValueDisplayed: 0  [0402]  (hidden comment: CRCW04020000Z0ED)
R205  ValueDisplayed: 0  [0402]  (hidden comment: CRCW04020000Z0ED)
R206  ValueDisplayed: 0  [0402]  (hidden comment: CRCW04020000Z0ED)
R207  ValueDisplayed: 0  [0402]  (hidden comment: CRCW04020000Z0ED)
R215  ValueDisplayed: 100k  [0402]  (hidden comment: CRCW0402100KFKED)
R257  ValueDisplayed: 100k  [0402]  (hidden comment: CRCW0402100KFKED)
RT1  value 10k  [DYA0002A-MFG]  (hidden comment: TMP6131DYAT)
RT2  value 10k  [DYA0002A-MFG]  (hidden comment: TMP6131DYAT)
RT3  value 10k  [DYA0002A-MFG]  (hidden comment: TMP6131DYAT)
RT4  value 10k  [DYA0002A-MFG]  (hidden comment: TMP6131DYAT)
U1  BQ78706PAP  [PAP0064N-MFG]
U2  TMUX1308PWR  [PW0016A-MFG]
U3  TMUX1308PWR  [PW0016A-MFG]

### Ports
CELL0 (bidir), CELL1 (bidir), CELL2 (bidir), CELL3 (bidir), CELL4 (bidir), CELL5 (bidir), CELL6 (bidir), CELL7 (bidir), CELL8 (bidir), CELL9 (bidir), CELL10 (bidir), CELL11 (bidir), CELL12 (bidir), CELL13 (bidir), CELL14 (bidir), CELL15 (bidir), CELL16 (bidir), CELL17 (bidir), CELL18 (bidir), CELL_BB (bidir), COMMH_N_OPT (bidir), COMMH_P_OPT (bidir), COMML_N_OPT (bidir), COMML_P_OPT (bidir), GND, ModuleN (bidir), ModuleP (bidir), NFAULT/GPIO2 (bidir), RX/GPIO0 (bidir), TS1 (bidir), TS2 (bidir), TS3 (bidir), TS4 (bidir), TS5 (bidir), TS6 (bidir), TS7 (bidir), TS8 (bidir), TS9 (bidir), TS10 (bidir), TS11 (bidir), TS12 (bidir), TS13 (bidir), TS14 (bidir), TX/GPIO1 (bidir)

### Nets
GND: C6.2 C9.2 C12.2 C18.1 C20.2 C24.2 C26.1 C28.2 C32.2 C38.1 C40.2 C43.2 C46.1 C48.2 C51.2 C55.1 C57.2 C60.2 C64.1 C66.2 C70.2 C78.2 C83.2 C87.2 C92.2 C100.2 C103.2 C107.2 C108.2 C109.2 C110.2 C111.2 C112.2 C113.2 C114.2 C115.1 C116.2 C117.2 C118.2 C119.2 C120.2 C121.2 C122.2 C123.2 C124.2 C125.1 C126.2 C127.2 C128.2 C129.2 C130.2 C131.2 C132.2 C133.2 C135.1 C136.2 C137.2 C138.2 C140.2 C147.1 C148.2 C149.2 C150.2 C151.2 C152.2 C191.1 D4.2(ANODE) D6.2(A) D7.2(A) D8.2(A) D9.2(A) D10.2(A) D11.3(GND) D12.3(GND) J1.4 J1.6 J1.10 J2.21 J2.25 Q1.2(S) Q2.2(S) R136.1 R137.1 R140.1 R148.1 R151.1 RT1.2 RT2.2 RT3.2 RT4.2 U1.42(VSS) U1.55(REF_VSS) U1.65(EP) U2.6(~{EN}) U2.8(GND) U3.6(~{EN}) U3.8(GND) ; port GND
AVDD: C55.2 C120.1 C140.1 R121.2 R122.2 R215.2 R257.2 U1.49(AVDD) U2.16(VDD) U3.16(VDD)
BAT: C1.2 C26.2 D1.1(K) D9.1(K) R36.2 R204.1 R207.1 U1.1(BAT)
BB: C61.2 C62.1 C67.2 C68.1 C75.2 C76.1 C79.2 C80.1 C84.2 C85.1 C89.2 C90.1 C96.2 C97.1 R79.1 U1.20(BB)
CB0: C93.2 C103.1 R84.2 R85.2 R86.2 R87.2 U1.39(CB0)
CB1: C72.2 C93.1 R69.2 R72.2 R76.2 R80.2 U1.37(CB1)
CB2: C52.2 C72.1 R55.2 R58.2 R62.2 R66.2 U1.35(CB2)
CB3: C34.2 C52.1 R42.2 R45.2 R48.2 R52.2 U1.33(CB3)
CB4: C15.2 C34.1 R27.2 R30.2 R33.2 R38.2 U1.31(CB4)
CB5: C2.2 C15.1 R13.2 R16.2 R20.2 R23.2 U1.29(CB5)
CB6: C2.1 C94.2 R1.2 R4.2 R7.2 R10.2 U1.27(CB6)
CB7: C73.2 C94.1 C97.2 R70.2 R73.2 R77.2 R81.2 U1.25(CB7)
CB8: C53.2 C73.1 C90.2 R56.2 R59.2 R63.2 R67.2 U1.23(CB8)
CB9: C35.2 C53.1 C85.2 R43.2 R46.2 R49.2 R53.2 U1.21(CB9)
CB10: C16.2 C35.1 C80.2 R28.2 R31.2 R34.2 R39.2 U1.18(CB10)
CB11: C3.2 C16.1 C76.2 R14.2 R17.2 R21.2 R24.2 U1.16(CB11)
CB12: C3.1 C68.2 C95.2 R2.2 R5.2 R8.2 R11.2 U1.14(CB12)
CB13: C62.2 C74.2 C95.1 R71.2 R74.2 R78.2 R82.2 R196.2 U1.12(CB13)
CB14: C54.2 C74.1 R57.2 R60.2 R64.2 R68.2 R196.1 R202.2 U1.10(CB14)
CB15: C36.2 C54.1 R44.2 R47.2 R50.2 R54.2 R197.2 R202.1 U1.8(BAT)
CB16: C17.2 C36.1 R29.2 R32.2 R35.2 R40.2 R197.1 R203.2 U1.6(BAT)
CB17: C4.2 C17.1 R15.2 R18.2 R22.2 R25.2 R198.2 R203.1 U1.4(BAT)
CB18: C1.1 C4.1 D10.1(K) R3.2 R6.2 R9.2 R12.2 R198.1 R204.2 U1.2(BAT)
CCAP_0: C91.2 C92.1
CCAP_1: C86.2 C87.1
CCAP_2: C82.2 C83.1
CCAP_3: C77.2 C78.1
CCAP_4: C69.2 C70.1
CCAP_5: C65.2 C66.1
CCAP_6: C59.2 C60.1
CCAP_7: C56.2 C57.1
CCAP_8: C50.2 C51.1
CCAP_9: C47.2 C48.1
CCAP_10: C42.2 C43.1
CCAP_11: C39.2 C40.1
CCAP_12: C31.2 C32.1
CCAP_13: C27.2 C28.1
CCAP_14: C23.2 C24.1
CCAP_15: C19.2 C20.1
CCAP_16: C11.2 C12.1
CCAP_17: C8.2 C9.1
CCAP_18: C5.2 C6.1
CCAP_BB: C99.2 C100.1
CELL0: C91.1 D4.1(CATHODE) D5.2(ANODE) J2.10 R84.1 R85.1 R86.1 R87.1 R139.1 ; port CELL0
CELL1: C86.1 D5.1(CATHODE) J2.31 R69.1 R72.1 R76.1 R80.1 R138.1 ; port CELL1
CELL2: C82.1 J2.11 R55.1 R58.1 R62.1 R66.1 R135.1 ; port CELL2
CELL3: C77.1 J2.32 R42.1 R45.1 R48.1 R52.1 R132.1 ; port CELL3
CELL4: C69.1 J2.12 R27.1 R30.1 R33.1 R38.1 R128.1 ; port CELL4
CELL5: C65.1 J2.33 R13.1 R16.1 R20.1 R23.1 R126.1 ; port CELL5
CELL6: C59.1 J2.13 R1.1 R4.1 R7.1 R10.1 R114.1 ; port CELL6
CELL7: C56.1 J2.34 R70.1 R73.1 R77.1 R81.1 R104.1 ; port CELL7
CELL8: C50.1 J2.14 R56.1 R59.1 R63.1 R67.1 R100.1 ; port CELL8
CELL9: C47.1 J2.35 R43.1 R46.1 R49.1 R53.1 R90.1 ; port CELL9
CELL10: C42.1 J2.36 R28.1 R31.1 R34.1 R39.1 R83.1 ; port CELL10
CELL11: C39.1 J2.16 R14.1 R17.1 R21.1 R24.1 R75.1 ; port CELL11
CELL12: C31.1 J2.37 R2.1 R5.1 R8.1 R11.1 R65.1 ; port CELL12
CELL13: C27.1 J2.17 R61.1 R71.1 R74.1 R78.1 R82.1 ; port CELL13
CELL14: C23.1 J2.38 R51.1 R57.1 R60.1 R64.1 R68.1 ; port CELL14
CELL15: C19.1 J2.18 R41.1 R44.1 R47.1 R50.1 R54.1 ; port CELL15
CELL16: C11.1 J2.39 R29.1 R32.1 R35.1 R37.1 R40.1 ; port CELL16
CELL17: C8.1 D7.1(K) J2.19 R15.1 R18.1 R22.1 R25.1 R26.1 ; port CELL17
CELL18: C5.1 D8.1(K) J2.40 R3.1 R6.1 R9.1 R12.1 R19.1 ; port CELL18
CELL_BB: C99.1 J2.15 R79.2 ; port CELL_BB
COMHN: C150.1 R193.1 U1.45(COMHN)
COMHP: C151.1 R180.1 U1.46(COMHP)
COMLN: C149.1 R192.2 U1.44(COMLN)
COMLP: C152.1 R179.2 U1.43(COMLP)
COMMH_N: R187.1 R189.1 R193.2 R194.1
COMMH_N_OPT: J4.2 R195.2 ; port COMMH_N_OPT
COMMH_P: R180.2 R181.1 R185.2 R187.2
COMMH_P_OPT: J4.1 R182.2 ; port COMMH_P_OPT
COMML_N: R186.1 R188.1 R191.2 R192.1
COMML_N_OPT: J3.2 R190.1 ; port COMML_N_OPT
COMML_P: R178.2 R179.1 R184.2 R186.2
COMML_P_OPT: J3.1 R177.1 ; port COMML_P_OPT
DVDD: C38.2 Q1.1(G) R136.2 U1.41(DVDD_CAP)
GPIO3: C119.1 R153.1 U1.64(GPIO3)
GPIO4: C124.1 R157.1 U1.63(GPIO4)
GPIO5: C129.1 R159.1 U1.62(GPIO5)
GPIO6: C133.1 R165.1 U1.61(GPIO6)
GPIO7: C115.2 R149.1 U1.60(GPIO7)
GPIO7_R: R146.1 R149.2 U2.3(D)
GPIO8: C135.2 R164.1 U1.59(GPIO8)
GPIO8_R: R161.1 R164.2 U3.3(D)
GPIO9: U1.58(GPIO9) U2.11(A0) U3.11(A0)
GPIO10: U1.57(GPIO10) U2.10(A1) U3.10(A1)
GPIO11: U1.56(GPIO11) U2.9(A2) U3.9(A2)
LDOIN: C18.2 Q3.3(E) U1.48(LDOIN)
ModuleN: J2.30 R140.2 ; port ModuleN
ModuleP: D6.1(K) J2.20 R36.1 R155.2 ; port ModuleP
ModuleP_L: C125.2 C191.2 Q3.2(C) R154.1
NFAULT/GPIO2: C114.1 Q2.1(G) R137.2 R150.1 R215.1 U1.53(~{FAULT}/GPIO2) ; port NFAULT/GPIO2
NPNB: Q3.1(B) U1.47(NPNB)
REF_CAP: C64.2 U1.54(REF_CAP)
RX/GPIO0: R257.1 U1.51(RX/GPIO0) ; port RX/GPIO0
TS1: C136.1 J2.1 U3.5(S5) ; port TS1
TS2: C130.1 J2.22 U3.4(S7) ; port TS2
TS3: C126.1 J2.2 U3.2(S6) ; port TS3
TS4: C121.1 J2.23 U3.1(S4) ; port TS4
TS5: C116.1 J2.3 U3.15(S2) ; port TS5
TS6: C111.1 J2.24 U3.14(S1) ; port TS6
TS7: C108.1 J2.4 U3.13(S0) ; port TS7
TS8: C137.1 J2.5 U2.5(S5) ; port TS8
TS9: C131.1 J2.26 U2.4(S7) ; port TS9
TS10: C127.1 J2.6 U2.2(S6) ; port TS10
TS11: C122.1 J2.27 U2.1(S4) ; port TS11
TS12: C117.1 J2.7 U2.15(S2) ; port TS12
TS13: C112.1 J2.28 U2.14(S1) ; port TS13
TS14: C109.1 J2.8 U2.13(S0) ; port TS14
TS15: C138.1 J1.3 R162.1 R165.2
TS16: C132.1 J1.5 R158.1 R159.2
TS17: C128.1 J1.7 R156.1 R157.2 RT1.1
TS18: C123.1 J1.8 R152.1 R153.2 RT2.1
TS19: C118.1 J1.1 R147.1 R150.2 RT3.1
TS20: C113.1 J1.2 R144.1 R145.2 RT4.1
TS_R1: R148.2 U3.12(S3)
TS_R2: R151.2 U2.12(S3)
TSREF: C46.2 R144.2 R146.2 R147.2 R152.2 R156.2 R158.2 R161.2 R162.2 U1.50(TSREF)
TX/GPIO1: C110.1 R145.1 U1.52(TX/GPIO1) ; port TX/GPIO1
VC0: C106.2 C107.1 R139.2 U1.40(VC0)
VC1: C105.2 C106.1 R138.2 U1.38(VC1)
VC2: C104.2 C105.1 R135.2 U1.36(VC2)
VC3: C102.2 C104.1 R132.2 U1.34(VC3)
VC4: C101.2 C102.1 R128.2 U1.32(VC4)
VC5: C98.2 C101.1 R126.2 U1.30(VC5)
VC6: C88.2 C98.1 R114.2 U1.28(VC6)
VC7: C81.2 C88.1 C96.1 R104.2 U1.26(VC7)
VC8: C71.2 C81.1 C89.1 R100.2 U1.24(VC8)
VC9: C63.2 C71.1 C84.1 R90.2 U1.22(VC9)
VC10: C58.2 C63.1 C79.1 R83.2 U1.19(VC10)
VC11: C49.2 C58.1 C75.1 R75.2 U1.17(VC11)
VC12: C45.2 C49.1 C67.1 R65.2 U1.15(VC12)
VC13: C37.2 C45.1 C61.1 R61.2 R199.2 U1.13(VC13)
VC14: C30.2 C37.1 R51.2 R199.1 R205.2 U1.11(VC14)
VC15: C22.2 C30.1 R41.2 R200.2 R205.1 U1.9(BAT)
VC16: C14.2 C22.1 R37.2 R200.1 R206.2 U1.7(BAT)
VC17: C7.2 C14.1 R26.2 R201.2 R206.1 U1.5(BAT)
VC18: C7.1 D1.2(A) R19.2 R201.1 R207.2 U1.3(BAT)
NetC147_2: C147.2 R184.1 R188.2
NetC148_1: C148.1 R185.1 R189.2
NetD2_1: D2.1(A) R121.1
NetD2_2: D2.2(K) Q1.3(D)
NetD3_1: D3.1(A) R122.1
NetD3_2: D3.2(K) Q2.3(D)
NetD11_1: D11.1(1_IO) R177.2 R178.1
NetD11_2: D11.2(2_IO) R190.2 R191.1
NetD12_1: D12.1(1_IO) R194.2 R195.1
NetD12_2: D12.2(2_IO) R181.2 R182.1
NetR154_2: R154.2 R155.1

Not connected (* = marked no-connect by the designer): J1 9*; J2 9* 29* 41(MNT_1)* 42(MNT_2)*; U2 7(NC)*; U3 7(NC)*

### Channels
A1: designators end in _A1; ports CELL0=CELL0_A1 CELL1=CELL1_A1 CELL2=CELL2_A1 CELL3=CELL3_A1 CELL4=CELL4_A1 CELL5=CELL5_A1 CELL6=CELL6_A1 CELL7=CELL7_A1 CELL8=CELL8_A1 CELL9=CELL9_A1 CELL10=CELL10_A1 CELL11=CELL11_A1 CELL12=CELL12_A1 CELL13=CELL13_A1 CELL14=CELL14_A1 CELL15=CELL15_A1 CELL16=CELL16_A1 CELL17=CELL17_A1 CELL18=CELL18_A1 CELL_BB=CELL_BB_A1 COMMH_N_OPT=COMMH_N_OPT COMMH_P_OPT=COMMH_P_OPT COMML_N_OPT=COMML_N_OPT COMML_P_OPT=COMML_P_OPT GND=GND ModuleN=ModuleN_A1 ModuleP=ModuleP_A1 NFAULT/GPIO2=NFAULT/GPIO2 RX/GPIO0=RX/GPIO0 TS1=TS1_A1 TS2=TS2_A1 TS3=TS3_A1 TS4=TS4_A1 TS5=TS5_A1 TS6=TS6_A1 TS7=TS7_A1 TS8=TS8_A1 TS9=TS9_A1 TS10=TS10_A1 TS11=TS11_A1 TS12=TS12_A1 TS13=TS13_A1 TS14=TS14_A1 TX/GPIO1=TX/GPIO1
A2: designators end in _A2; ports CELL0=CELL0_A2 CELL1=CELL1_A2 CELL2=CELL2_A2 CELL3=CELL3_A2 CELL4=CELL4_A2 CELL5=CELL5_A2 CELL6=CELL6_A2 CELL7=CELL7_A2 CELL8=CELL8_A2 CELL9=CELL9_A2 CELL10=CELL10_A2 CELL11=CELL11_A2 CELL12=CELL12_A2 CELL13=CELL13_A2 CELL14=CELL14_A2 CELL15=CELL15_A2 CELL16=CELL16_A2 CELL17=CELL17_A2 CELL18=CELL18_A2 CELL_BB=CELL_BB_A2 COMMH_N_OPT=COMMH_N_OPT COMMH_P_OPT=COMMH_P_OPT COMML_N_OPT=COMML_N_OPT COMML_P_OPT=COMML_P_OPT GND=GND ModuleN=ModuleN_A2 ModuleP=ModuleP_A2 NFAULT/GPIO2=NFAULT/GPIO2_A2 RX/GPIO0=RX/GPIO0_A2 TS1=TS1_A2 TS2=TS2_A2 TS3=TS3_A2 TS4=TS4_A2 TS5=TS5_A2 TS6=TS6_A2 TS7=TS7_A2 TS8=TS8_A2 TS9=TS9_A2 TS10=TS10_A2 TS11=TS11_A2 TS12=TS12_A2 TS13=TS13_A2 TS14=TS14_A2 TX/GPIO1=TX/GPIO1_A2
A3: designators end in _A3; ports CELL0=CELL0_A3 CELL1=CELL1_A3 CELL2=CELL2_A3 CELL3=CELL3_A3 CELL4=CELL4_A3 CELL5=CELL5_A3 CELL6=CELL6_A3 CELL7=CELL7_A3 CELL8=CELL8_A3 CELL9=CELL9_A3 CELL10=CELL10_A3 CELL11=CELL11_A3 CELL12=CELL12_A3 CELL13=CELL13_A3 CELL14=CELL14_A3 CELL15=CELL15_A3 CELL16=CELL16_A3 CELL17=CELL17_A3 CELL18=CELL18_A3 CELL_BB=CELL_BB_A3 COMMH_N_OPT=COMMH_N_OPT COMMH_P_OPT=COMMH_P_OPT COMML_N_OPT=COMML_N_OPT COMML_P_OPT=COMML_P_OPT GND=GND ModuleN=ModuleN_A3 ModuleP=ModuleP_A3 NFAULT/GPIO2=NFAULT/GPIO2_A3 RX/GPIO0=RX/GPIO0_A3 TS1=TS1_A3 TS2=TS2_A3 TS3=TS3_A3 TS4=TS4_A3 TS5=TS5_A3 TS6=TS6_A3 TS7=TS7_A3 TS8=TS8_A3 TS9=TS9_A3 TS10=TS10_A3 TS11=TS11_A3 TS12=TS12_A3 TS13=TS13_A3 TS14=TS14_A3 TX/GPIO1=TX/GPIO1_A3
A4: designators end in _A4; ports CELL0=CELL0_A4 CELL1=CELL1_A4 CELL2=CELL2_A4 CELL3=CELL3_A4 CELL4=CELL4_A4 CELL5=CELL5_A4 CELL6=CELL6_A4 CELL7=CELL7_A4 CELL8=CELL8_A4 CELL9=CELL9_A4 CELL10=CELL10_A4 CELL11=CELL11_A4 CELL12=CELL12_A4 CELL13=CELL13_A4 CELL14=CELL14_A4 CELL15=CELL15_A4 CELL16=CELL16_A4 CELL17=CELL17_A4 CELL18=CELL18_A4 CELL_BB=CELL_BB_A4 COMMH_N_OPT=COMMH_N_OPT COMMH_P_OPT=COMMH_P_OPT COMML_N_OPT=COMML_N_OPT COMML_P_OPT=COMML_P_OPT GND=GND ModuleN=ModuleN_A4 ModuleP=ModuleP_A4 NFAULT/GPIO2=NFAULT/GPIO2_A4 RX/GPIO0=RX/GPIO0_A4 TS1=TS1_A4 TS2=TS2_A4 TS3=TS3_A4 TS4=TS4_A4 TS5=TS5_A4 TS6=TS6_A4 TS7=TS7_A4 TS8=TS8_A4 TS9=TS9_A4 TS10=TS10_A4 TS11=TS11_A4 TS12=TS12_A4 TS13=TS13_A4 TS14=TS14_A4 TX/GPIO1=TX/GPIO1_A4

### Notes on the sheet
- Cell balancing
- Cell voltage
- 100mA CB current
- Input ESD protection
- (near C18) Power Cap
- 100k pullup only for AFE1 in CAN
- Status indiation
  1 shutdown: No on
  2 wake and normal: 2 Green
  3 wake and abnormal: 1 green
- USE RB160MM-60TFTR
- Cell temperature
- NPN Power Supply-150V
- 20 Thermistor input with 400ms refresh
  TSx is input to GPIO ADC
  TCx_C is connector input
  TSR1&2 is set >125C/<1k(0.8k) for PTC ERT-J1VG103GA
  TSR1&2 is set <-40C/ <5k(3k) for TMP6131DECR
- 1.Two TMUX populated to sense 20~|2(2 self test) temp per AFE for full temp using BQ78718.
  2.One TMUX populated to sense 14~
  5(1 self test) temp per AFE for full temp using BQ78706 by GPIO1~7 and TMUX(GPIO8~
  1)
  3.No TMUX populated to sense 11 temp per AFE for half temp using BQ78706(7+1BB) by GPIO1~8. TS14+TS7 is near to GPIO7/8
- Communication
- 1. TS15~TS20, 3 GND
  2. TS14,TS4, 1 GND
  3. One connector not used 40pin
- Cell channel config
  12*4: short 6 resistors
  13*4: short 5 resistors
  18*3: No shart and SMT BQ79718
- ESD652？

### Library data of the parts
C1-C4 C15-C17 C34-C36 C52-C54 C62 C68 C72-C74 C76 C80 C85 C90 C93-C95 C97 C103 C108-C124 C126-C133 C135-C138 C140 = CMP-0006356-2: CAP, CERM, 0.1 uF, 50 V, +/- 10%, X7R, AEC-Q200 Grade 1, 0402; Manufacturer: MuRata; TaMin_C: -55°C; Polarized: N; SizeAreaWB_mm2: 3; Value1: Unknown; U/M: EA; Value: 0.1uF; TaMax_C: 125°C; SizeZ_mm: 0.6; SizeX_mm: 1; SizeY_mm: 0.5; Value2: 50V; AEC Qualified: Y; Cap_F: 100nF; AEC Category: Q200
C5 C6 C8 C9 C11 C12 C19 C20 C23 C24 C27 C28 C31 C32 C39 C40 C42 C43 C47 C48 C50 C51 C56 C57 C59 C60 C65 C66 C69 C70 C77 C78 C82 C83 C86 C87 C91 C92 C99 C100 = CMP-0096840-1: Cap Ceramic 22nF 100V X7R 10% Pad SMD 0603 +125°C Automotive T/R; Manufacturer: TDK; AEC Grade: Grade 1; SizeZ_mm: 1.1mm; Tolerance_%: 0.1%; AEC Qualified: Yes; TempCo: 0.15
C7 C14 C22 C30 C37 C45 C49 C58 C61 C63 C67 C71 C75 C79 C81 C84 C88 C89 C96 C98 C101 C102 C104-C107 = CMP-0006361-2: CAP, CERM, 4700 pF, 50 V, +/- 10%, X7R, AEC-Q200 Grade 1, 0402; Manufacturer: MuRata; TaMin_C: -55°C; Polarized: N; SizeAreaWB_mm2: 3; Value1: Unknown; U/M: EA; Value: 4700pF; TaMax_C: 125°C; SizeZ_mm: 0.6; SizeX_mm: 1; SizeY_mm: 0.5; Value2: 50V; AEC Qualified: Y; Cap_F: 4.7nF; AEC Category: Q200
C18 = CMP-0080738-1: CAP, CERM, 4.7 µF, 10 V,+/- 5%, X7R, AEC-Q200 Grade 1, 0805; Manufacturer: Kemet; AEC Grade: 1; AEC Qualified: Y; SizeZ_mm: 1.45; VDC_V: 10V; SizeAreaWB_mm2: 6.75; SizeArea_mm2: 2.5; AEC Category: Q200; Value: 4.7uF; TaMax_C: 125°C; Polarized: N; TaMin_C: -55°C; SizeY_mm: 1.25; U/M: EA; SizeX_mm: 2; Cap_Case: 0805
C26 = CMP-0084773-1: CAP, CERM, 0.01 µF, 100 V,+/- 10%, X7R, AEC-Q200 Grade 1, 0603; Manufacturer: MuRata; SizeArea_mm2: 1.28; ValueDisplayed: 0.01µF; Polarized: N; AEC Grade: 1; Value2: 100V; SizeY_mm: 0.8; Cap_Case: 0603; TaMax_C: 125°C; Value: 0.01uF; SizeAreaWB_mm2: 4.68; TaMin_C: -55°C; CompType: Capacitor; AEC Category: Q200; U/M: EA; AEC Qualified: Y; SizeX_mm: 1.6
C38 C55 = CMP-0007136-5: CAP, CERM, 1 uF, 16 V, +/- 10%, X7R, AEC-Q200 Grade 1, 0603; Manufacturer: MuRata; TaMin_C: -55°C; Polarized: N; SizeAreaWB_mm2: 4.68; Value1: Unknown; U/M: EA; Value: 1uF; TaMax_C: 125°C; SizeZ_mm: 1; SizeX_mm: 1.6; SizeY_mm: 0.8; Value2: 16V; SizeArea_mm2: 1.28; AEC Qualified: Y; AEC Category: Q200
C46 C64 = CMP-0007138-4: CAP, CERM, 0.47 uF, 16 V, +/- 10%, X7R, AEC-Q200 Grade 1, 0603; Manufacturer: MuRata; Polarized: N; CompType: Capacitor; Value: 0.47uF; U/M: EA; Cap_F: 470nF; Value1: Unknown; VDC_V: 16V; TaMin_C: -55°C; TaMax_C: 125°C; AEC Category: Q200; AEC Qualified: Y; AEC Grade: 1; SizeAreaWB_mm2: 4.68; SizeX_mm: 1.6; SizeY_mm: 0.8; SizeArea_mm2: 1.28
C125 C191 = CMP-0119652-1: WCAP-CSGP Multilayer Ceramic Chip Capacitor, General Purpose, size 1206, X7R, 100nF, 100VDC; Manufacturer: Wurth Elektronik; Capacitance Tolerance: +/-10%; Case/Size Code: 1206; Dissipation Factor: 2.5%; Insulation Resistance: 1GOhm; Rated Voltage (DC): 100V; Technical Reference: X7R1206104K100DFCT10000
C147 C148 = CMP-0007143-4: CAP, CERM, 0.01 uF, 50 V, +/- 10%, X7R, AEC-Q200 Grade 1, 0603; Manufacturer: MuRata; TaMin_C: -55°C; Polarized: N; SizeAreaWB_mm2: 4.68; Value1: Unknown; U/M: EA; Value: 0.01uF; TaMax_C: 125°C; SizeZ_mm: 1; SizeX_mm: 1.6; SizeY_mm: 0.8; Value2: 50V; SizeArea_mm2: 1.28; AEC Qualified: Y; AEC Category: Q200
C149-C152 = CMP-0860329-1: CAP, CERM, 220 pF, 50 V,+/- 5%, X7R, 0603; Manufacturer: Samsung Electro-Mechanics; TaMin_C: -55°C; Polarized: N; SizeAreaWB_mm2: 4.68; U/M: EA; Value: 220pF; TaMax_C: 125°C; SizeZ_mm: 1; SizeX_mm: 1.6; SizeY_mm: 0.8; Value2: 50V; SizeArea_mm2: 1.28; CompType: Capacitor; AEC Category: Q200
D1 = CMP-0029023-2: Diode, Superfast Rectifier, 150 V, 1 A, SMA; Manufacturer: Diodes Inc.; TJmax_C: 150°C; Vr_V: 150V; Value2: 0.92V; SizeX_mm: 5.59; Green_REACh: Incomplete; SizeAreaWB_mm2: 37.3428; Value: 150V; Vf_V: 920mV; Green_Lifecycle: Not Set; Value1: 1A; SizeZ_mm: 2.87; SizeArea_mm2: 16.3228; SizeY_mm: 2.92; AEC Category: Q101; RJC_CperW: 25
D2 D3 = CMP-0002888-2: LED, Green, SMD; Manufacturer: Lite-On; Type: AlInGaP; Vf_V: 2V; Io_A: 20mA; Value1: W
D4 D5 = CMP-0033054-1: SMD16PL Series 60 V 1 A Surface Mount Schottky Rectifier - SOD-123FL; Manufacturer: Micro Commercial Co; AEC Qualified: No; SizeZ_mm: 1.35mm; TJmax_C: 125°C; Vf_V: 60V; Cap_F: 40pF; Forward Current: 1A; Max Surge Forward Current: 30A; Peak Reverse Current: 0.1mA
D6-D8 D10 = CMP-0005590-3: Diode, TVS, Uni, 85 V, 137 Vc, SMB; Manufacturer: Diodes Inc.; Vc: 137V; SizeX_mm: 5.6; SizeArea_mm2: 21.336; SizeAreaWB_mm2: 44.156; Ipp: 4.4A; SizeZ_mm: 2.6; Value1: 600W; Vbr_Min: 94.4V; AEC Category: Q101; SizeY_mm: 3.81; Vbr_Max: 108.2V
D9 = CMP-0084976-1: Diode, TVS, Uni, 85 V, 137 Vc, 400 W, 2.9 A, SMA; Manufacturer: Littelfuse; SizeX_mm: 5.59; Vbr_Min: 94.4V; Value1: 137V; AEC Category: Q101; SizeY_mm: 2.92; SizeZ_mm: 2.87; Ipp: 2.9A; RJA_CperW: 120; Vbr_Max: 104V; SizeAreaWB_mm2: 37.3428; AEC Qualified: N; SizeArea_mm2: 16.3228; Ppk: 400W
D11 D12 = CMP-0122986-1: 18V two-channel bidirectional ESD protection diode; Manufacturer: Texas Instruments; AEC Qualified: No; SizeZ_mm: 1.12mm; Ipp: 5.5A; Ppk: 176W; Breakdown Voltage: 19V; Cap_F: 4pF; Clamping Voltage: 25V; Number Of Channels: 2; Standoff Height: 0.01mm; TJmax_C: +150°C
J1 = CMP-0075634-2: Header(Shrouded), 1.27mm, 5x2, Gold, SMT; Manufacturer: Samtec; Pitch_mm: 1.27; Gender: Male; Cert_CSA: Y; Current_A: 3.3A; Row_Count: 2
J2 = CMP-0123118-1: 2.00mm Wafer, Right Angle Connector, 40pins, Key-A With CPA Feature; Manufacturer: BEIJIDA ELECTRONICS TECHNOLOGY; ContactFinish: Tin,Nickel; Current_A: 3A; Row_Count: 2; Voltage_V: 60V; AEC Qualified: No; Conn Gender: Male; DUT-Pitch_mm: 2mm; SizeZ_mm: 9.6mm
J3 J4 = CMP-0002337-1: Header, 100mil, 2x1, Tin, TH; Manufacturer: Sullins Connector Solutions; CNHeader: TRUE; Current_A: 3A; Green_Lifecycle: Not Set; Shrouded: N; Gender: Male; Green_REACh: Incomplete; Voltage_V: 1.8kV; Row_Count: 1; Pitch_mm: 2.54; CT: FALSE; Cert_UL: Y
Q1 Q2 = CMP-0086180-1: MOSFET, N-CH, 20 V, 0.2 A, AEC-Q101, SC-89; Alternate Manufacturer: None; Manufacturer: Rohm; AEC Category: Q101; Value: 20V; SizeY_mm: 1.6; Vgs_V: 8V; SizeArea_mm2: 2.56; SizeAreaWB_mm2: 6.76; Value2: ? nC; ChMode: Enhancement; ChType: N; Value1: ? ohm; SizeZ_mm: 0.8; AEC Qualified: Y; IdsMax_A: 200mA
Q3 = CMP-0000504-4: Transistor, NPN, 150 V, 1 A, AEC-Q101, DPAK; Manufacturer: Diodes Inc.; PartNumber: ZXTN4004KTC; CompType: BJT; IcRated_A: 1A; PNP: 0; SizeArea_mm2: 64.8114; TaMax_C: 150°C; Vceo_V: 150V; TaMin_C: -55°C; SizeX_mm: 9.91; SizeY_mm: 6.54; SizeZ_mm: 2.29; Value1: 1 A; AEC Category: Q101; Vcesat1_V: 250mV; NPN: 1; SizeAreaWB_mm2: 101.7114; AEC Qualified: Y; Value: 150 V
R1-R18 R20-R25 R27-R35 R38-R40 R42-R50 R52-R60 R62-R64 R66-R74 R76-R78 R80-R82 R84-R87 = CMP-0020585-3: RES, 68, 5%, 0.125 W, AEC-Q200 Grade 0, 0805; Manufacturer: RESI; Power_W: 125mW; TempCo: 200 ppm/C; Value_Code: 68R0; Value: 68; EIA_Code: E24; SizeX_mm: 2; SizeY_mm: 1.25; SizeZ_mm: 1.45; Value2: 0.125W; SizeArea_mm2: 2.5; AEC Qualified: Y; VDC_V: 150V; AEC Category: Q200; AEC Grade: 0
R19 R26 R37 R41 R51 R61 R65 R75 R83 R90 R100 R104 R114 R126 R128 R132 R135 R138 R139 = CMP-0026071-3: RES, 1.00 k, 1%, 0.063 W, AEC-Q200 Grade 0, 0402; Manufacturer: Vishay-Dale; Power_W: 63mW; TempCo: 100 ppm/C; Value_Code: 1k00; Value: 1.00k; EIA_Code: E96; Res_ohm: 1k; SizeX_mm: 1; SizeY_mm: 0.5; SizeZ_mm: 0.6; Value2: 0.063W; AEC Qualified: Y; VDC_V: 50V; AEC Category: Q200; AEC Grade: 0
R36 = CMP-0021368-3: RES, 60.4, 1%, 0.125 W, AEC-Q200 Grade 0, 0805; Manufacturer: Vishay-Dale; Power_W: 125mW; TempCo: 100 ppm/C; Value_Code: 60R4; Value: 60.4; EIA_Code: E96; SizeX_mm: 2; SizeY_mm: 1.25; SizeZ_mm: 1.45; Value2: 0.125W; SizeArea_mm2: 2.5; AEC Qualified: Y; VDC_V: 150V; AEC Category: Q200; AEC Grade: 0
R79 = CMP-0026436-2: RES, 511, 1%, 0.063 W, AEC-Q200 Grade 0, 0402; Manufacturer: Vishay-Dale; Power_W: 63mW; TempCo: 100 ppm/C; Value_Code: 511R; Value: 511; EIA_Code: E96; SizeX_mm: 1; SizeY_mm: 0.5; SizeZ_mm: 0.6; Value2: 0.063W; AEC Qualified: Y; VDC_V: 50V; AEC Category: Q200; AEC Grade: 0
R121 R122 = CMP-0026918-5: RES, 3.3 k, 5%, 0.063 W, AEC-Q200 Grade 0, 0402; Manufacturer: Vishay-Dale; Power_W: 63mW; TempCo: 200 ppm/C; Value_Code: 3k30; Value: 3.3k; EIA_Code: E24; SizeX_mm: 1; SizeY_mm: 0.5; SizeZ_mm: 0.6; Value2: 0.063W; AEC Qualified: Y; VDC_V: 50V; AEC Category: Q200; AEC Grade: 0
R136 R137 = CMP-0025702-4: RES, 10 M, 5%, 0.1 W, AEC-Q200 Grade 0, 0603; Manufacturer: Vishay-Dale; Power_W: 100mW; TempCo: 200 ppm/C; Value_Code: 10M0; Value: 10Meg; EIA_Code: E24; SizeX_mm: 1.6; SizeY_mm: 0.8; SizeZ_mm: 1; Value2: 0.1W; SizeArea_mm2: 1.28; AEC Qualified: Y; VDC_V: 75V; AEC Category: Q200; AEC Grade: 0
R140 R196-R207 = CMP-0026822-3: RES, 0, 5%, 0.063 W, AEC-Q200 Grade 0, 0402; Manufacturer: Vishay-Dale; Power_W: 63mW; TempCo: 200 ppm/C; Value_Code: 0000; Value: 0; EIA_Code: E24; SizeX_mm: 1; SizeY_mm: 0.5; SizeZ_mm: 0.6; Value2: 0.063W; AEC Qualified: Y; VDC_V: 50V; AEC Category: Q200
R144 R146 R147 R152 R156 R158 R161 R162 = CMP-0025958-3: RES, 10.0 k, 1%, 0.063 W, AEC-Q200 Grade 0, 0402; Manufacturer: Vishay-Dale; Power_W: 63mW; TempCo: 100 ppm/C; Value_Code: 10k0; Value: 10.0k; EIA_Code: E96; Res_ohm: 10k; SizeX_mm: 1; SizeY_mm: 0.5; SizeZ_mm: 0.6; Value2: 0.063W; AEC Qualified: Y; VDC_V: 50V; AEC Category: Q200; AEC Grade: 0
R145 R148-R151 R153 R157 R159 R164 R165 = CMP-0026852-3: RES, 1.0 k, 5%, 0.063 W, AEC-Q200 Grade 0, 0402; Manufacturer: Vishay-Dale; Power_W: 63mW; TempCo: 200 ppm/C; Value_Code: 1k00; Value: 1.0k; EIA_Code: E24; Res_ohm: 1k; SizeX_mm: 1; SizeY_mm: 0.5; SizeZ_mm: 0.6; Value2: 0.063W; AEC Qualified: Y; VDC_V: 50V; AEC Category: Q200; AEC Grade: 0
R154 = CMP-0016209-3: RES, 100, 1%, 0.75 W, AEC-Q200 Grade 0, 2010; Manufacturer: Vishay-Dale; Power_W: 750mW; TempCo: 100 ppm/C; Value_Code: 100R; Value: 100; EIA_Code: E96; SizeX_mm: 5; SizeY_mm: 2.5; SizeZ_mm: 1.66; Value2: 0.75W; SizeArea_mm2: 12.5; AEC Qualified: Y; VDC_V: 400V; AEC Category: Q200; AEC Grade: 0
R155 = CMP-0016302-3: RES, 200, 1%, 0.75 W, AEC-Q200 Grade 0, 2010; Manufacturer: Vishay-Dale; Power_W: 750mW; TempCo: 100 ppm/C; Value_Code: 200R; Value: 200; EIA_Code: E96; SizeX_mm: 5; SizeY_mm: 2.5; SizeZ_mm: 1.66; Value2: 0.75W; SizeArea_mm2: 12.5; AEC Qualified: Y; VDC_V: 400V; AEC Category: Q200; AEC Grade: 0
R177 R182 R190 R195 = CMP-0025885-5: RES, 0, 5%, 0.1 W, 0603; Manufacturer: Yageo; Power_W: 100mW; TempCo: 200 ppm/C; Value_Code: 0000; Value: 0; EIA_Code: E24; SizeX_mm: 1.6; SizeY_mm: 0.8; SizeZ_mm: 1; Value2: 0.1W; SizeArea_mm2: 1.28; AEC Qualified: N; VDC_V: 75V; AEC Category: Q200; SizeAreaWB_mm2: 4.68
R178 R181 R194 = CMP-0025825-4: RES, 51, 5%, 0.1 W, AEC-Q200 Grade 0, 0603; Manufacturer: Vishay-Dale; Power_W: 100mW; TempCo: 200 ppm/C; Value_Code: 51R0; Value: 51; EIA_Code: E24; SizeX_mm: 1.6; SizeY_mm: 0.8; SizeZ_mm: 1; Value2: 0.1W; SizeArea_mm2: 1.28; AEC Qualified: Y; VDC_V: 75V; AEC Category: Q200; AEC Grade: 0
R179 R180 R192 R193 = CMP-0025874-4: RES, 0, 5%, 0.1 W, AEC-Q200 Grade 0, 0603; Manufacturer: Panasonic; Power_W: 100mW; TempCo: 600 ppm/C; Value_Code: 0000; Value: 0; EIA_Code: E24; SizeX_mm: 1.6; SizeY_mm: 0.8; SizeZ_mm: 1; Value2: 0.1W; SizeArea_mm2: 1.28; AEC Qualified: Y; AEC Category: Q200; VDC_V: 50V; SizeAreaWB_mm2: 4.68
R184 R185 R188 R189 = CMP-0025823-4: RES, 510, 5%, 0.1 W, AEC-Q200 Grade 0, 0603; Manufacturer: Vishay-Dale; Power_W: 100mW; TempCo: 200 ppm/C; Value_Code: 510R; Value: 510; EIA_Code: E24; SizeX_mm: 1.6; SizeY_mm: 0.8; SizeZ_mm: 1; Value2: 0.1W; SizeArea_mm2: 1.28; AEC Qualified: Y; VDC_V: 75V; AEC Category: Q200; AEC Grade: 0
R186 R187 = CMP-0022680-4: RES, 1.00 k, 1%, 0.1 W, 0603; Manufacturer: Panasonic; Power_W: 100mW; TempCo: 100 ppm/C; Value_Code: 1k00; Value: 1.00k; EIA_Code: E96; Res_ohm: 1k; SizeX_mm: 1.6; SizeY_mm: 0.8; SizeZ_mm: 1; Value2: 0.1W; SizeArea_mm2: 1.28; VDC_V: 75V; AEC Category: Q200; U/M: EA
R191 = CMP-0025825-4: RES, 51, 5%, 0.1 W, AEC-Q200 Grade 0, 0603; Manufacturer: Vishay-Dale; TempCo: 200 ppm/C; Value: 51; SizeX_mm: 1.6; SizeY_mm: 0.8; SizeZ_mm: 1; Value2: 0.1W; SizeArea_mm2: 1.28; AEC Qualified: Y; VDC_V: 75V; AEC Category: Q200; AEC Grade: 0; Power_W: 100mW; Value_Code: 51R0; EIA_Code: E24
R215 R257 = CMP-0025950-3: RES, 100 k, 1%, 0.063 W, AEC-Q200 Grade 0, 0402; Manufacturer: Vishay-Dale; Power_W: 63mW; TempCo: 100 ppm/C; Value: 100k; EIA_Code: E96; SizeX_mm: 1; SizeY_mm: 0.5; SizeZ_mm: 0.6; Value2: 0.063W; AEC Qualified: Y; VDC_V: 50V; AEC Category: Q200; AEC Grade: 0
RT1-RT4 = CMP-0091865-2: ±1% tolerance 10kΩ linear thermistor available in 0402 and 0603 package options 2-SOT-5X3 -40 to 125; Manufacturer: Texas Instruments; Max Current: 400uA; AEC Qualified: No; TJmax_C: +155°C; TaMin_C: -40°C; TempCo: 6400ppm/°C; TaMax_C: +125°C; VDC_V: 5.5V; SizeZ_mm: 0.77mm; AEC Category: Q200; CompType: IC
U1 = CMP-0122614-1: Functional Safety-Compliant 14S Battery Monitor; Manufacturer: Texas Instruments; SizeZ_mm: 1.2mm; AEC Qualified: No; Max Supply Voltage: 70V; Min Supply Voltage: 9V; Nominal Supply Current: 3.5mA; Number Of Cells: 14; Standoff Height: 0.05mm; TaMax_C: +125°C; TaMin_C: -40°C; TJmax_C: +150°C
U2 U3 = CMP-0090991-1: 5-V, 8: 1, 1-channel general-purpose multiplexer with 1.8-V logic control 16-TSSOP -40 to 125; Manufacturer: Texas Instruments; Max Supply Voltage: 5.5V; AEC Qualified: No; PositionCount: 1; Min Supply Voltage: 1.62V; -3Db Bandwith: 350-500MHz; Mux Demux Ratio: 8:1; Nominal Supply Current: 1uA; SizeZ_mm: 1.2mm; TaMin_C: -40°C; TaMax_C: +125°C; Standoff Height: 0.05mm; TJmax_C: +150°C; On State Resistance: 75-650Ω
